Omron CX-Programmer project 新工程 (CX-Programmer 7.30)

# PLC 新PLC1: CP1H XA

## Global symbols (name address type ; comment)
0.00 BOOL  ; 风扇开关
100.00 BOOL  ; 风扇
100.01 BOOL  ; 电机1
100.02 BOOL  ; 500W
100.03 BOOL  ; 1000W
100.04 BOOL  ; 2000W
100.05 BOOL  ; 冷却电机
100.06 BOOL  ; 冷却电磁阀
100.07 BOOL  ; 回流电磁阀
2 CHANNEL  ; 恒温箱温度采集通道
D0 CHANNEL  ; 恒温箱温度采集
D10 CHANNEL  ; 水箱温度采集
D12 CHANNEL  ; 温度2浮点数
D14 CHANNEL  ; 常数90
D16 CHANNEL  ; 常数5
D18 CHANNEL  ; 常数1
D2 CHANNEL  ; 温度1浮点数
D20 CHANNEL  ; 常数10
D22 CHANNEL  ; 浮点数10
D24 CHANNEL  ; 浮点数5
D26 CHANNEL  ; 浮点数2
D28 CHANNEL  ; 浮点数2.5
D30 CHANNEL  ; 浮点数1
D32 CHANNEL  ; 恒温箱检测温度
D34 CHANNEL  ; 水箱检测温度
D36 CHANNEL  ; 恒温箱设定温度
D38 CHANNEL  ; 水箱温度设定
D4 CHANNEL  ; 常数2
D40 CHANNEL  ; 水箱设定温度-5
D42 CHANNEL  ; 水箱设定温度减2.5
D44 CHANNEL  ; 水箱设定温度1减1
D46 CHANNEL  ; 浮点数90
D48 CHANNEL  ; 恒温箱设定温度+5
D50 CHANNEL  ; 恒温箱设定温度-5
D52 CHANNEL  ; 水箱温度+5
D54 CHANNEL  ; 水箱设定温度+1
D56 CHANNEL  ; 恒温箱设定温度-1
W0.00 BOOL  ; 加温自动
W0.01 BOOL  ; 冷却自动
W0.02 BOOL  ; 水箱温度过高报警解除加温
W0.03 BOOL  ; 水箱温度过低报警解除冷却
W0.04 BOOL  ; 解除报警
W0.05 BOOL  ; 恒温箱开关
W0.06 BOOL  ; 恒温箱温度高于设定温度5度以上
W0.07 BOOL  ; 恒温箱温度低于设定温度5度以下
W1.00 BOOL  ; 水箱温度高于设定温度5度以上
W1.01 BOOL  ; 水箱温度低于设定温度以下
W1.02 BOOL  ; 手动自动切换
W3.00 BOOL  ; 切换电磁阀

## Program 新程序1 (cyclic task 0)
Local symbols
D324D42 REAL
F UINT

### Section 段1

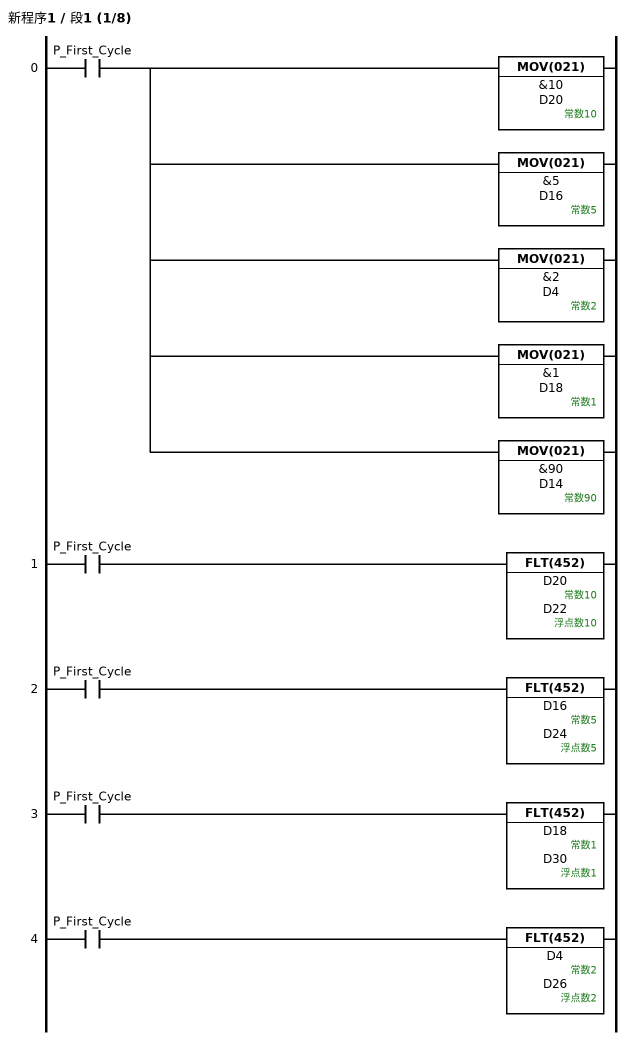
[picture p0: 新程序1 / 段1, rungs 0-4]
; rung 0
LD P_First_Cycle
MOV(021) &10 D20  ; 常数10
MOV(021) &5 D16  ; 常数5
MOV(021) &2 D4  ; 常数2
MOV(021) &1 D18  ; 常数1
MOV(021) &90 D14  ; 常数90
; rung 1
LD P_First_Cycle
FLT(452) D20 D22  ; 常数10, 浮点数10
; rung 2
LD P_First_Cycle
FLT(452) D16 D24  ; 常数5, 浮点数5
; rung 3
LD P_First_Cycle
FLT(452) D18 D30  ; 常数1, 浮点数1
; rung 4
LD P_First_Cycle
FLT(452) D4 D26  ; 常数2, 浮点数2

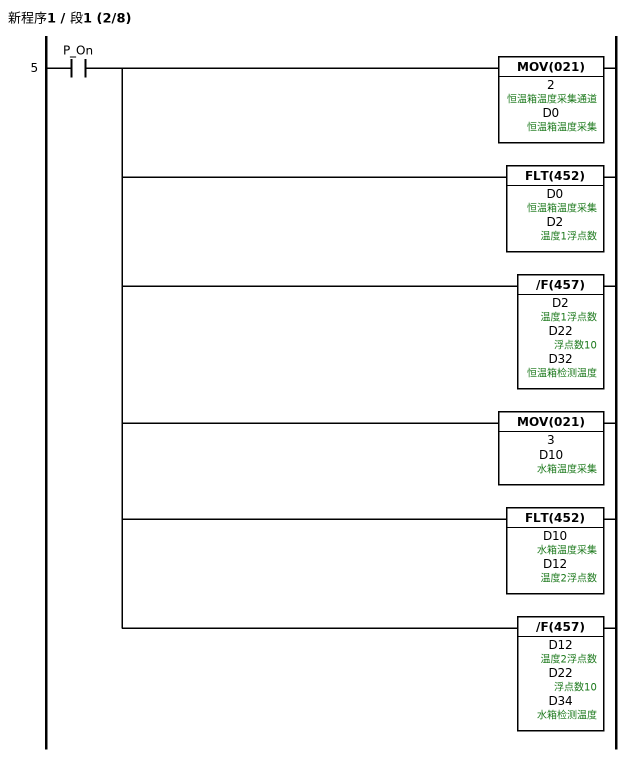
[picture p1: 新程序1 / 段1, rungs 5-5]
; rung 5
LD P_On
MOV(021) 2 D0  ; 恒温箱温度采集通道, 恒温箱温度采集
FLT(452) D0 D2  ; 恒温箱温度采集, 温度1浮点数
/F(457) D2 D22 D32  ; 温度1浮点数, 浮点数10, 恒温箱检测温度
MOV(021) 3 D10  ; 水箱温度采集
FLT(452) D10 D12  ; 水箱温度采集, 温度2浮点数
/F(457) D12 D22 D34  ; 温度2浮点数, 浮点数10, 水箱检测温度

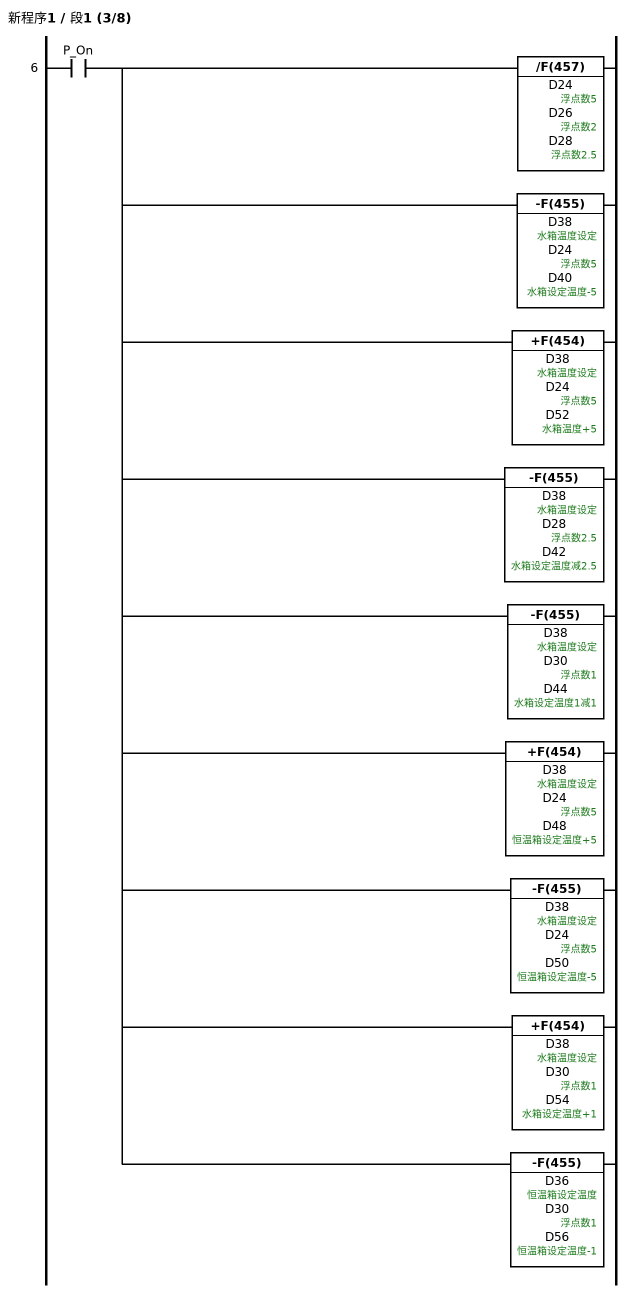
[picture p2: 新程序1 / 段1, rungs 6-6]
; rung 6
LD P_On
/F(457) D24 D26 D28  ; 浮点数5, 浮点数2, 浮点数2.5
-F(455) D38 D24 D40  ; 水箱温度设定, 浮点数5, 水箱设定温度-5
+F(454) D38 D24 D52  ; 水箱温度设定, 浮点数5, 水箱温度+5
-F(455) D38 D28 D42  ; 水箱温度设定, 浮点数2.5, 水箱设定温度减2.5
-F(455) D38 D30 D44  ; 水箱温度设定, 浮点数1, 水箱设定温度1减1
+F(454) D38 D24 D48  ; 水箱温度设定, 浮点数5, 恒温箱设定温度+5
-F(455) D38 D24 D50  ; 水箱温度设定, 浮点数5, 恒温箱设定温度-5
+F(454) D38 D30 D54  ; 水箱温度设定, 浮点数1, 水箱设定温度+1
-F(455) D36 D30 D56  ; 恒温箱设定温度, 浮点数1, 恒温箱设定温度-1

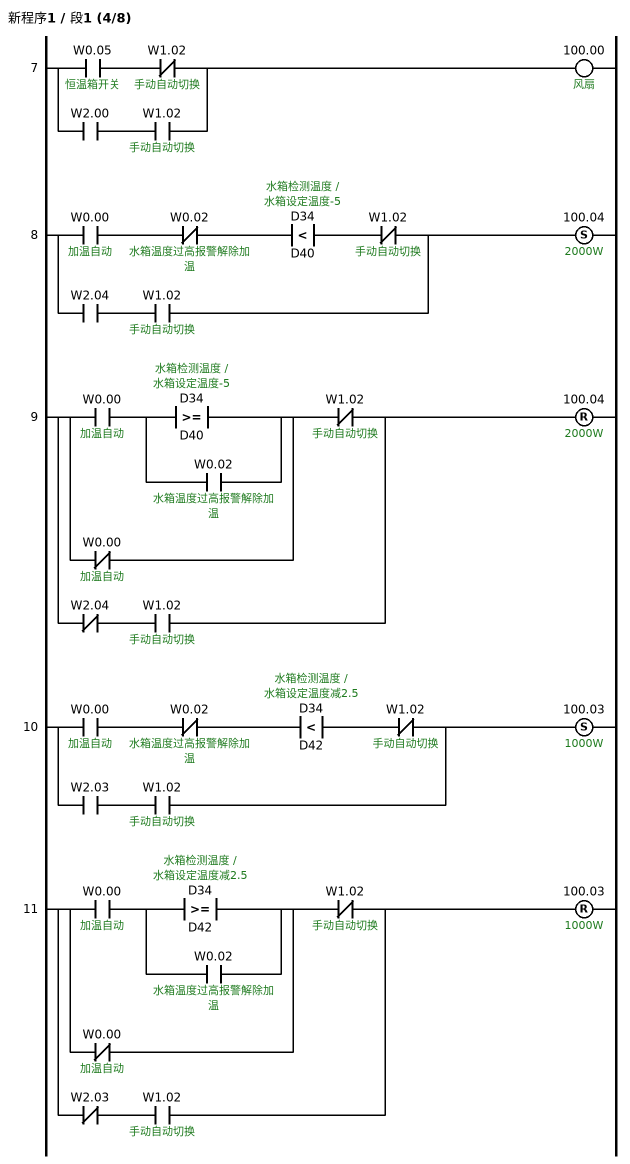
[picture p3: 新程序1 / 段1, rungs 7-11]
; rung 7
LD W0.05  ; 恒温箱开关
ANDNOT W1.02  ; 手动自动切换
LD W2.00
AND W1.02  ; 手动自动切换
ORLD
OUT 100.00  ; 风扇
; rung 8
LD W0.00  ; 加温自动
ANDNOT W0.02  ; 水箱温度过高报警解除加温
AND<F(331) D34 D40  ; 水箱检测温度, 水箱设定温度-5
ANDNOT W1.02  ; 手动自动切换
LD W2.04
AND W1.02  ; 手动自动切换
ORLD
SET 100.04  ; 2000W
; rung 9
LD W0.00  ; 加温自动
LD>=F(334) D34 D40  ; 水箱检测温度, 水箱设定温度-5
OR W0.02  ; 水箱温度过高报警解除加温
ANDLD
ORNOT W0.00  ; 加温自动
ANDNOT W1.02  ; 手动自动切换
LDNOT W2.04
AND W1.02  ; 手动自动切换
ORLD
RSET 100.04  ; 2000W
; rung 10
LD W0.00  ; 加温自动
ANDNOT W0.02  ; 水箱温度过高报警解除加温
AND<F(331) D34 D42  ; 水箱检测温度, 水箱设定温度减2.5
ANDNOT W1.02  ; 手动自动切换
LD W2.03
AND W1.02  ; 手动自动切换
ORLD
SET 100.03  ; 1000W
; rung 11
LD W0.00  ; 加温自动
LD>=F(334) D34 D42  ; 水箱检测温度, 水箱设定温度减2.5
OR W0.02  ; 水箱温度过高报警解除加温
ANDLD
ORNOT W0.00  ; 加温自动
ANDNOT W1.02  ; 手动自动切换
LDNOT W2.03
AND W1.02  ; 手动自动切换
ORLD
RSET 100.03  ; 1000W

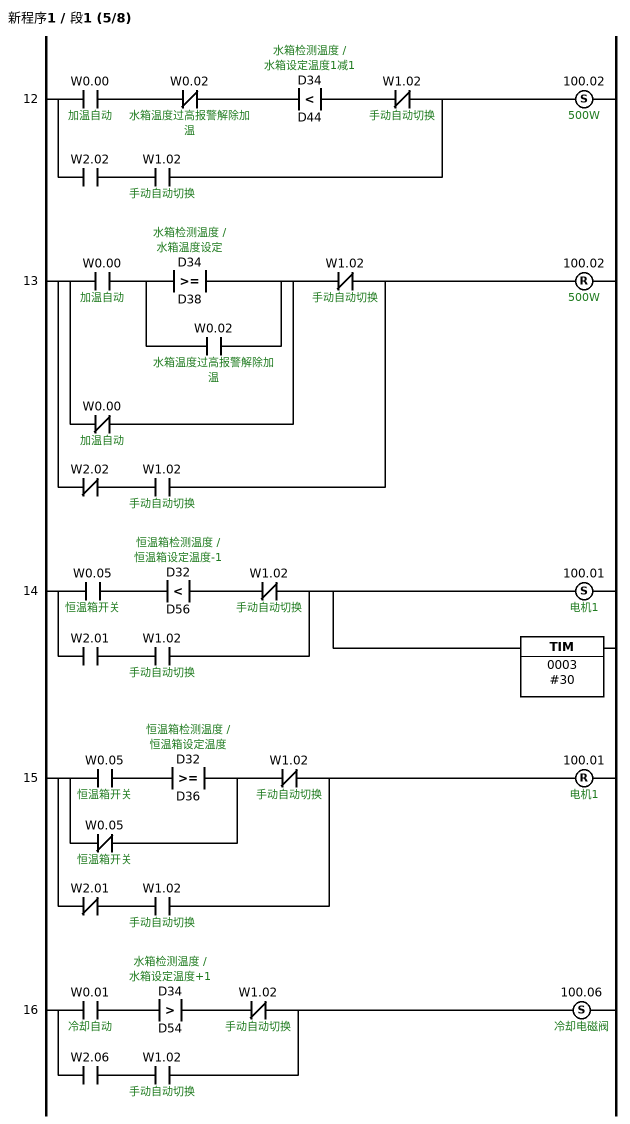
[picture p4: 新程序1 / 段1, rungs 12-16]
; rung 12
LD W0.00  ; 加温自动
ANDNOT W0.02  ; 水箱温度过高报警解除加温
AND<F(331) D34 D44  ; 水箱检测温度, 水箱设定温度1减1
ANDNOT W1.02  ; 手动自动切换
LD W2.02
AND W1.02  ; 手动自动切换
ORLD
SET 100.02  ; 500W
; rung 13
LD W0.00  ; 加温自动
LD>=F(334) D34 D38  ; 水箱检测温度, 水箱温度设定
OR W0.02  ; 水箱温度过高报警解除加温
ANDLD
ORNOT W0.00  ; 加温自动
ANDNOT W1.02  ; 手动自动切换
LDNOT W2.02
AND W1.02  ; 手动自动切换
ORLD
RSET 100.02  ; 500W
; rung 14
LD W0.05  ; 恒温箱开关
AND<F(331) D32 D56  ; 恒温箱检测温度, 恒温箱设定温度-1
ANDNOT W1.02  ; 手动自动切换
LD W2.01
AND W1.02  ; 手动自动切换
ORLD
SET 100.01  ; 电机1
TIM 0003 #30
; rung 15
LD W0.05  ; 恒温箱开关
AND>=F(334) D32 D36  ; 恒温箱检测温度, 恒温箱设定温度
ORNOT W0.05  ; 恒温箱开关
ANDNOT W1.02  ; 手动自动切换
LDNOT W2.01
AND W1.02  ; 手动自动切换
ORLD
RSET 100.01  ; 电机1
; rung 16
LD W0.01  ; 冷却自动
AND>F(333) D34 D54  ; 水箱检测温度, 水箱设定温度+1
ANDNOT W1.02  ; 手动自动切换
LD W2.06
AND W1.02  ; 手动自动切换
ORLD
SET 100.06  ; 冷却电磁阀

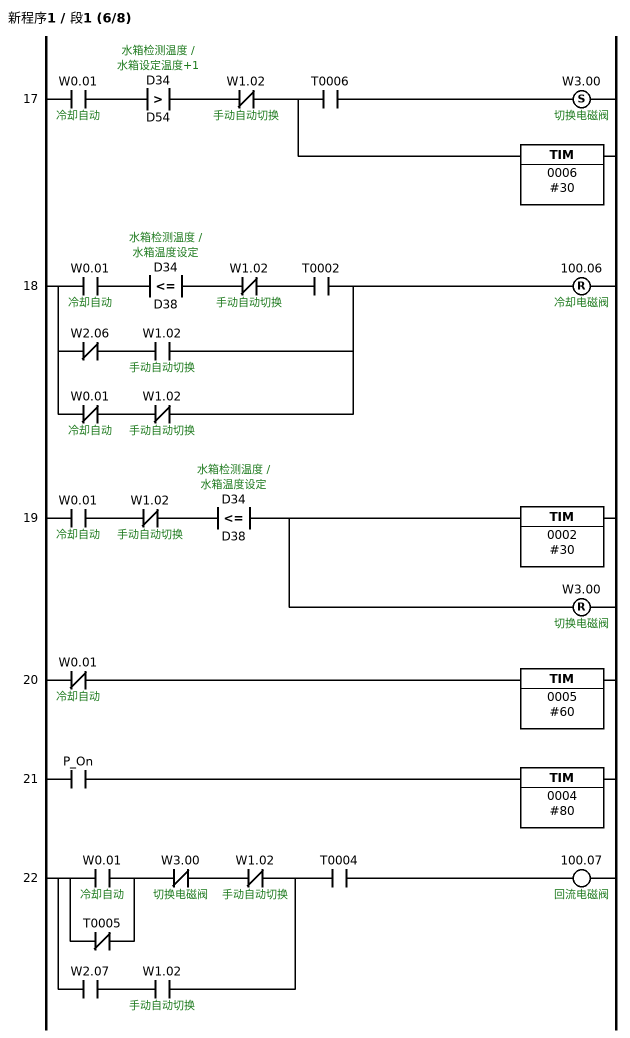
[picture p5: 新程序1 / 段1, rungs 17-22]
; rung 17
LD W0.01  ; 冷却自动
AND>F(333) D34 D54  ; 水箱检测温度, 水箱设定温度+1
ANDNOT W1.02  ; 手动自动切换
OUT TR0
AND T0006
SET W3.00  ; 切换电磁阀
LD TR0
TIM 0006 #30
; rung 18
LD W0.01  ; 冷却自动
AND<=F(332) D34 D38  ; 水箱检测温度, 水箱温度设定
ANDNOT W1.02  ; 手动自动切换
AND T0002
LDNOT W2.06
AND W1.02  ; 手动自动切换
ORLD
LDNOT W0.01  ; 冷却自动
ANDNOT W1.02  ; 手动自动切换
ORLD
RSET 100.06  ; 冷却电磁阀
; rung 19
LD W0.01  ; 冷却自动
ANDNOT W1.02  ; 手动自动切换
AND<=F(332) D34 D38  ; 水箱检测温度, 水箱温度设定
TIM 0002 #30
RSET W3.00  ; 切换电磁阀
; rung 20
LDNOT W0.01  ; 冷却自动
TIM 0005 #60
; rung 21
LD P_On
TIM 0004 #80
; rung 22
LD W0.01  ; 冷却自动
ORNOT T0005
ANDNOT W3.00  ; 切换电磁阀
ANDNOT W1.02  ; 手动自动切换
LD W2.07
AND W1.02  ; 手动自动切换
ORLD
AND T0004
OUT 100.07  ; 回流电磁阀

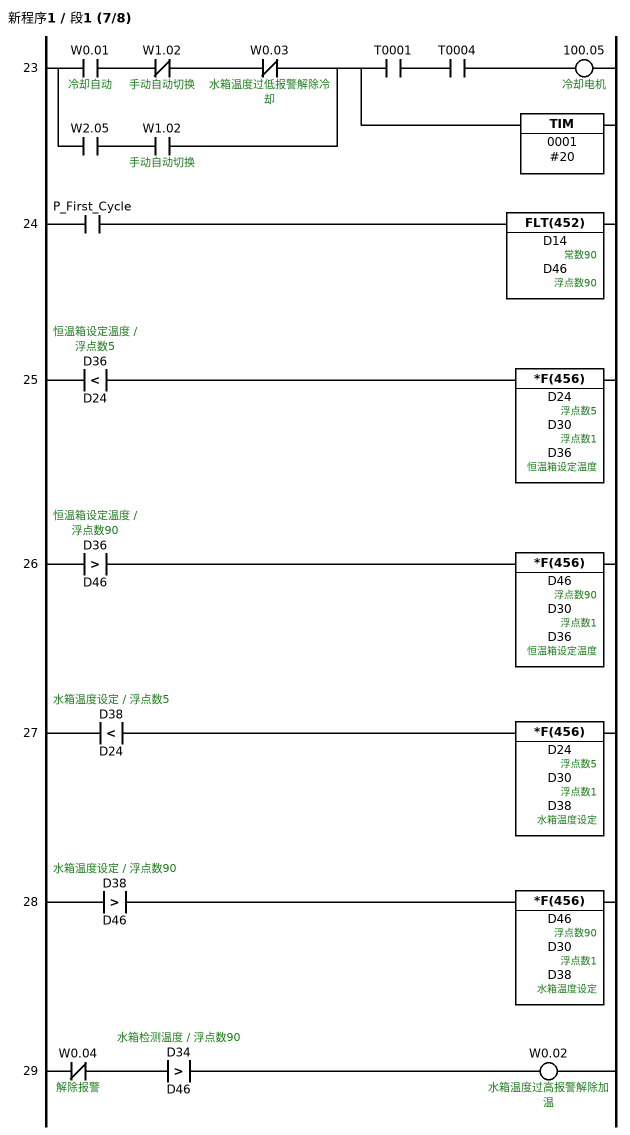
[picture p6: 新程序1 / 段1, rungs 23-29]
; rung 23
LD W0.01  ; 冷却自动
ANDNOT W1.02  ; 手动自动切换
ANDNOT W0.03  ; 水箱温度过低报警解除冷却
LD W2.05
AND W1.02  ; 手动自动切换
ORLD
OUT TR0
AND T0001
AND T0004
OUT 100.05  ; 冷却电机
LD TR0
TIM 0001 #20
; rung 24
LD P_First_Cycle
FLT(452) D14 D46  ; 常数90, 浮点数90
; rung 25
LD<F(331) D36 D24  ; 恒温箱设定温度, 浮点数5
*F(456) D24 D30 D36  ; 浮点数5, 浮点数1, 恒温箱设定温度
; rung 26
LD>F(333) D36 D46  ; 恒温箱设定温度, 浮点数90
*F(456) D46 D30 D36  ; 浮点数90, 浮点数1, 恒温箱设定温度
; rung 27
LD<F(331) D38 D24  ; 水箱温度设定, 浮点数5
*F(456) D24 D30 D38  ; 浮点数5, 浮点数1, 水箱温度设定
; rung 28
LD>F(333) D38 D46  ; 水箱温度设定, 浮点数90
*F(456) D46 D30 D38  ; 浮点数90, 浮点数1, 水箱温度设定
; rung 29
LDNOT W0.04  ; 解除报警
AND>F(333) D34 D46  ; 水箱检测温度, 浮点数90
OUT W0.02  ; 水箱温度过高报警解除加温

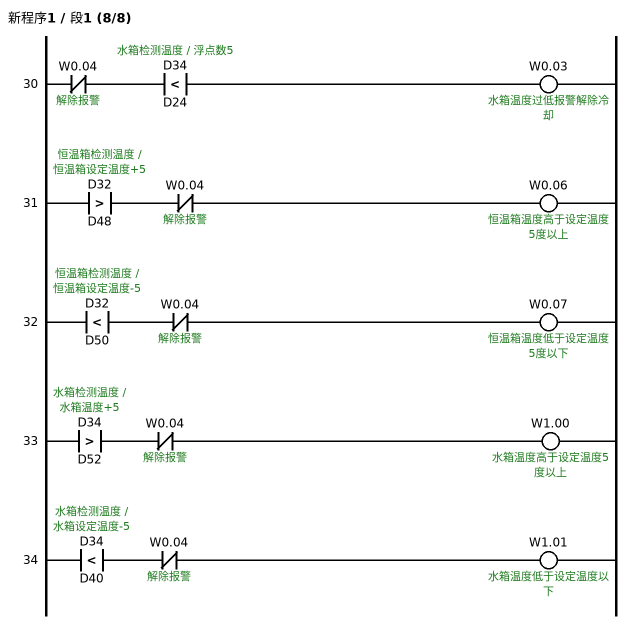
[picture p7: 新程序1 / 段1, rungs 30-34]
; rung 30
LDNOT W0.04  ; 解除报警
AND<F(331) D34 D24  ; 水箱检测温度, 浮点数5
OUT W0.03  ; 水箱温度过低报警解除冷却
; rung 31
LD>F(333) D32 D48  ; 恒温箱检测温度, 恒温箱设定温度+5
ANDNOT W0.04  ; 解除报警
OUT W0.06  ; 恒温箱温度高于设定温度5度以上
; rung 32
LD<F(331) D32 D50  ; 恒温箱检测温度, 恒温箱设定温度-5
ANDNOT W0.04  ; 解除报警
OUT W0.07  ; 恒温箱温度低于设定温度5度以下
; rung 33
LD>F(333) D34 D52  ; 水箱检测温度, 水箱温度+5
ANDNOT W0.04  ; 解除报警
OUT W1.00  ; 水箱温度高于设定温度5度以上
; rung 34
LD<F(331) D34 D40  ; 水箱检测温度, 水箱设定温度-5
ANDNOT W0.04  ; 解除报警
OUT W1.01  ; 水箱温度低于设定温度以下

### Section END
; rung 0
END(001)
